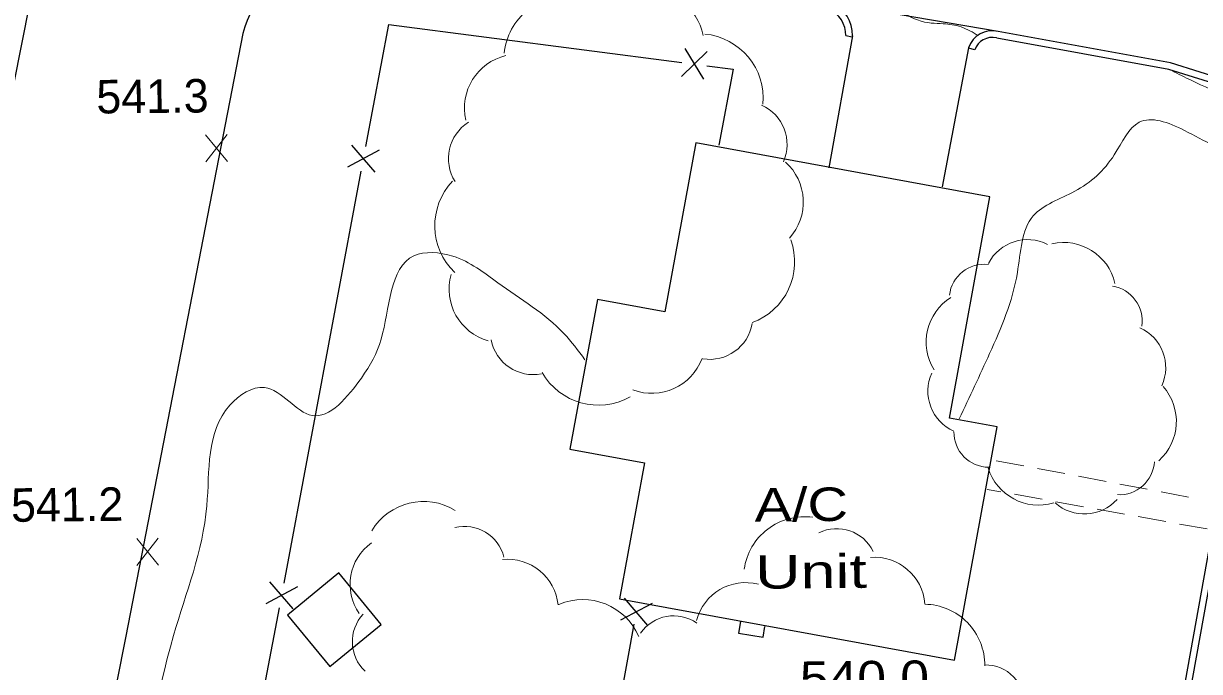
# Model space of a CAD drawing. Extents: x 2361708 to 2370558, y 6977955 to 6991887.
# Drawn here: x 2366425.5 to 2366593.7, y 6983677.6 to 6983770.4 of the extents above; entities that cross this region are included whole.
import ezdxf

# ---------------------------------------------------------------- set-up
doc = ezdxf.new("R2010")
doc.units = 0
doc.header["$LTSCALE"] = 1.9
for name, color, linetype, lineweight in [('11', 7, 'Continuous', 25), ('13', 7, 'Continuous', 13), ('17', 7, 'Continuous', 25), ('2', 7, 'Continuous', 25), ('20', 7, 'Continuous', 25), ('23', 7, 'Continuous', 25), ('29', 7, 'Continuous', 13), ('31', 7, 'Continuous', 13), ('35', 7, 'Continuous', 13)]:
    doc.layers.add(name, color=color, linetype=linetype, lineweight=lineweight)

msp = doc.modelspace()

# ---------------------------------------------------------------- linework, layer by layer
at = {"layer": '11'}
for points in [[(2366557.945, 6983713.908), (2366563.744, 6983745.544), (2366521.668, 6983753.274), (2366517.228, 6983729.091), (2366507.581, 6983730.869), (2366503.644, 6983709.47), (2366514.323, 6983707.512), (2366510.749, 6983688.047), (2366558.664, 6983679.263), (2366564.787, 6983712.653)], [(2366470.601, 6983691.735), (2366463.259, 6983685.685), (2366469.319, 6983678.332), (2366476.662, 6983684.373)]]:
    msp.add_lwpolyline(points, close=True, dxfattribs=at)
at = {"layer": '13'}
for p, q in [((2366568.58, 6983707.059), (2366564.643, 6983707.791)), ((2366574.471, 6983705.945), (2366570.544, 6983706.687)), ((2366580.362, 6983704.831), (2366576.435, 6983705.573)), ((2366563.342, 6983703.699), (2366565.305, 6983703.347)), ((2366567.269, 6983702.996), (2366571.206, 6983702.283)), ((2366586.253, 6983703.717), (2366582.326, 6983704.459)), ((2366592.144, 6983702.603), (2366588.216, 6983703.345)), ((2366573.169, 6983701.932), (2366577.107, 6983701.219)), ((2366579.069, 6983700.868), (2366583.007, 6983700.155)), ((2366584.97, 6983699.804), (2366588.907, 6983699.091)), ((2366590.87, 6983698.74), (2366594.808, 6983698.028))]:
    msp.add_line(p, q, dxfattribs=at)
at = {"layer": '17'}
for p, q in [((2366519.617, 6983762.805), (2366523.303, 6983766.36)), ((2366522.791, 6983762.395), (2366520.13, 6983766.77)), ((2366476.376, 6983752.233), (2366471.849, 6983749.83)), ((2366475.786, 6983749.088), (2366472.438, 6983752.976)), ((2366462.755, 6983690.271), (2366473.804, 6983749.249)), ((2366464.66, 6983689.729), (2366460.133, 6983687.315)), ((2366464.07, 6983686.583), (2366460.723, 6983690.461)), ((2366514.825, 6983684.236), (2366511.468, 6983688.104)), ((2366515.405, 6983687.381), (2366510.888, 6983684.958)), ((2366510.154, 6983669.641), (2366512.853, 6983684.397))]:
    msp.add_line(p, q, dxfattribs=at)
for points in [[(2366474.471, 6983752.785), (2366477.735, 6983770.207), (2366519.659, 6983764.786)], [(2366523.233, 6983764.32), (2366527.008, 6983763.836), (2366524.951, 6983752.935)], [(2366449.807, 6983628.004), (2366460.167, 6983676.465), (2366462.089, 6983686.734)]]:
    msp.add_lwpolyline(points, dxfattribs=at)
at = {"layer": '2'}
for p, q in [((2366564.908, 6983769.227), (2366541.089, 6983773.27)), ((2366544.073, 6983768.608), (2366540.683, 6983749.705)), ((2366543.113, 6983768.639), (2366544.055, 6983768.448)), ((2366560.671, 6983766.886), (2366556.91, 6983746.99)), ((2366561.583, 6983766.585), (2366560.661, 6983766.846)), ((2366586.861, 6983649.24), (2366604.772, 6983749.085)), ((2366587.803, 6983649.069), (2366605.714, 6983748.914))]:
    msp.add_line(p, q, dxfattribs=at)
for points in [[(2366412.45, 6983703.193), (2366434.505, 6983814.108), (2366426.801, 6983813.424), (2366404.245, 6983726.755), (2366372.306, 6983610.926), (2366341.663, 6983499.678), (2366310.838, 6983396.1)], [(2366456.855, 6983768.958), (2366440.106, 6983682.665), (2366424.189, 6983602.459), (2366413.719, 6983550.917), (2366405.327, 6983504.885)], [(2366598.058, 6983762.052), (2366589.572, 6983764.721), (2366564.908, 6983769.227)], [(2366597.767, 6983761.139), (2366589.341, 6983763.789), (2366564.737, 6983768.285)]]:
    msp.add_lwpolyline(points, dxfattribs=at)
for centre, radius, start, end in [((2366477.417, 6983762.96), 21.418, 84.11911, 163.73748), ((2366539.16, 6983768.749), 3.955, 358.35667, 66.89654), ((2366539.16, 6983768.749), 4.915, 358.35667, 66.89654), ((2366564.048, 6983765.778), 3.554, 75.98916, 161.84111), ((2366564.048, 6983765.778), 2.594, 75.98916, 161.84111)]:
    msp.add_arc(centre, radius, start, end, dxfattribs=at)
at = {"layer": '23'}
msp.add_line((2366528.05, 6983684.792), (2366527.786, 6983683.099), dxfattribs=at)
msp.add_lwpolyline([(2366527.786, 6983683.099), (2366531.322, 6983682.553), (2366531.557, 6983684.085)], dxfattribs=at)
at = {"layer": '29'}
for centre, radius, start, end in [((2366503.435, 6983765.141), 9.234, 84.00965, 174.00965), ((2366515.153, 6983767.245), 7.698, 10.67843, 100.67843), ((2366522.076, 6983759.669), 9.234, 354.60882, 84.60882), ((2366496.273, 6983758.29), 7.698, 103.25187, 193.25187), ((2366528.568, 6983753.071), 6.152, 336.02524, 66.02524), ((2366492.432, 6983751.041), 6.152, 122.38701, 212.38701), ((2366529.344, 6983744.814), 7.698, 317.93359, 47.93359), ((2366493.552, 6983741.433), 9.234, 136.33427, 226.33427), ((2366526.57, 6983736.238), 9.234, 289.93585, 19.93585), ((2366569.118, 6983733.155), 6.28, 62.77074, 152.77074), ((2366574.289, 6983731.496), 7.532, 12.895, 102.895), ((2366562.937, 6983730.896), 5.019, 83.29294, 173.29294), ((2366494.073, 6983732.349), 7.698, 164.14525, 254.14525), ((2366580.491, 6983727.819), 5.019, 351.16992, 81.16992), ((2366562.151, 6983724.777), 7.532, 121.97963, 211.97963), ((2366523.656, 6983728.453), 6.152, 260.62154, 350.62154), ((2366582.605, 6983721.114), 6.28, 335.65893, 65.65893), ((2366498.422, 6983726.267), 6.152, 190.91145, 280.91145), ((2366515.369, 6983725.138), 7.698, 249.35327, 339.35327), ((2366507.724, 6983724.977), 9.234, 209.39007, 299.39007), ((2366561.137, 6983717.75), 6.28, 155.82763, 245.82763), ((2366582.885, 6983713.411), 7.532, 311.75515, 41.75515), ((2366563.612, 6983711.881), 5.019, 179.4664, 269.4664), ((2366570.69, 6983708.975), 7.532, 196.88522, 286.88522), ((2366582.268, 6983707.952), 5.019, 266.66531, 356.66531), ((2366482.735, 6983693.263), 8.699, 58.67537, 148.67537), ((2366577.243, 6983706.457), 6.28, 228.16783, 318.16783), ((2366537.209, 6983691.078), 8.699, 82.21467, 172.21467), ((2366488.576, 6983692.603), 5.796, 13.80949, 103.80949), ((2366541.816, 6983692.279), 5.796, 25.92118, 115.92118), ((2366479.448, 6983690.107), 7.253, 125.08288, 215.08288), ((2366494.742, 6983686.443), 7.253, 5.7249, 95.7249), ((2366547.206, 6983686.737), 7.253, 4.45383, 94.45383), ((2366528.779, 6983683.099), 7.253, 75.30159, 165.30159), ((2366505.488, 6983679.231), 8.699, 23.01119, 113.01119), ((2366554.3, 6983678.561), 8.699, 359.28997, 89.28997), ((2366478.323, 6983681.886), 5.796, 136.79738, 226.79738), ((2366518.507, 6983679.805), 5.796, 55.17647, 145.17647), ((2366563.024, 6983672.785), 5.796, 0.00055, 90.00055)]:
    msp.add_arc(centre, radius, start, end, dxfattribs=at)
at = {"layer": '31'}
for p, q in [((2366454.66, 6983750.606), (2366451.543, 6983754.457)), ((2366451.58, 6983750.577), (2366454.623, 6983754.486)), ((2366444.8, 6983692.83), (2366441.683, 6983696.68)), ((2366441.72, 6983692.8), (2366444.763, 6983696.71))]:
    msp.add_line(p, q, dxfattribs=at)
at = {"layer": '35'}
for points in [[(2366634.791, 6983919.569), (2366632.667, 6983912.539), (2366627.202, 6983898.356), (2366624.039, 6983887.106), (2366616.496, 6983871.663), (2366613.136, 6983862.14), (2366609.482, 6983856.205), (2366604.22, 6983852.195), (2366602.436, 6983848.438), (2366604.988, 6983846.192), (2366609.012, 6983842.61), (2366607.842, 6983834.219), (2366604.316, 6983824.374), (2366600.197, 6983816.855), (2366595.104, 6983813.926), (2366586.855, 6983813.848), (2366579.375, 6983814.807), (2366565.709, 6983816.387), (2366552.761, 6983818.243), (2366538.688, 6983819.56), (2366528.389, 6983821.472), (2366516.562, 6983822.139), (2366503.671, 6983825.346), (2366492.754, 6983824.962), (2366486.612, 6983826.254), (2366479.358, 6983831.816), (2366476.585, 6983837.429), (2366473.459, 6983845.36), (2366472.047, 6983851.857), (2366469.955, 6983851.087), (2366464.652, 6983848.116), (2366456.29, 6983849.427), (2366449.947, 6983851.717), (2366444.634, 6983854.106), (2366440.213, 6983856.324), (2366439.877, 6983854.881), (2366437.568, 6983844.288), (2366434.981, 6983834.523), (2366431.199, 6983822.067), (2366424.733, 6983799.634), (2366418.881, 6983780.807), (2366413.681, 6983760.847), (2366407.995, 6983739.342), (2366403.268, 6983718.016), (2366399.542, 6983701.839), (2366394.896, 6983679.284), (2366389.396, 6983656.12), (2366384.274, 6983633.281), (2366382.176, 6983616.25), (2366377.896, 6983593.058), (2366374.864, 6983570.218), (2366370.936, 6983546.83), (2366369.353, 6983533.434), (2366367.804, 6983522.799), (2366367.692, 6983521.998), (2366366.792, 6983516.709), (2366366.128, 6983509.792), (2366367.472, 6983509.385), (2366370.916, 6983514.278), (2366374.314, 6983517.631), (2366381.278, 6983525.637), (2366394.175, 6983533.32), (2366404.166, 6983536.455), (2366409.203, 6983534.753), (2366412.734, 6983529.367), (2366412.225, 6983522.982), (2366409.904, 6983513.569), (2366408.594, 6983499.946), (2366407.465, 6983488.314), (2366406.028, 6983481.58), (2366403.731, 6983476.068)], [(2366485.979, 6983819.178), (2366491.127, 6983816.247), (2366497.776, 6983813.32), (2366506.035, 6983809.238), (2366516.566, 6983804.868), (2366522.554, 6983799.955), (2366522.228, 6983793.232), (2366511.842, 6983788.552), (2366499.129, 6983787.691), (2366484.539, 6983787.642), (2366478.993, 6983786.16), (2366477.97, 6983785.39), (2366469.928, 6983783.543), (2366464.932, 6983781.985), (2366460.007, 6983782.469), (2366451.957, 6983787.693), (2366446.912, 6983795.635), (2366444.296, 6983806.651), (2366442.084, 6983819.48), (2366439.958, 6983825.4), (2366437.556, 6983825.557), (2366435.491, 6983820.757), (2366433.254, 6983812.046), (2366430.05, 6983799.815), (2366424.514, 6983785.841), (2366419.166, 6983764.549), (2366412.066, 6983740.291), (2366405.175, 6983714.073), (2366400.657, 6983691.81), (2366392.571, 6983657.801), (2366386.433, 6983629.101), (2366384.991, 6983612.557), (2366382.778, 6983592.915), (2366378.809, 6983577.036), (2366376.571, 6983564.184), (2366377.538, 6983561.393), (2366376.072, 6983551.529), (2366377.363, 6983549.311), (2366379.325, 6983551.08), (2366383.487, 6983558.33), (2366388.543, 6983565.118), (2366393.945, 6983569.14), (2366402.789, 6983577.104), (2366412.027, 6983583.723), (2366418.005, 6983584.98), (2366420.808, 6983580.446), (2366420.744, 6983570.415), (2366420.747, 6983554.294), (2366418.434, 6983532.531), (2366415.774, 6983515.755), (2366412.918, 6983503.757), (2366410.989, 6983493.138), (2366409.593, 6983483.234), (2366407.334, 6983475.733)], [(2366564.357, 6983805.103), (2366573.894, 6983801.214), (2366584.724, 6983797.137), (2366592.02, 6983794.396), (2366597.447, 6983791.588), (2366601.823, 6983786.759), (2366601.806, 6983782.239), (2366597.508, 6983776.758), (2366590.083, 6983774.137), (2366581.034, 6983772.92), (2366571.363, 6983772.898), (2366560.996, 6983772.64), (2366553.955, 6983772.673), (2366551.048, 6983772.365), (2366553.363, 6983770.877), (2366557.068, 6983770.342), (2366559.622, 6983769.877), (2366562.074, 6983768.64)], [(2366589.813, 6983763.604), (2366592.516, 6983762.239), (2366598.044, 6983759.342), (2366600.986, 6983754.95), (2366599.414, 6983753.044), (2366591.574, 6983755.07), (2366585.093, 6983756.238), (2366581.537, 6983751.594), (2366575.867, 6983746.35), (2366569.93, 6983742.833), (2366567.667, 6983734.711), (2366563.687, 6983723.123), (2366559.365, 6983713.791)], [(2366505.793, 6983722.252), (2366502.797, 6983725.994), (2366493.357, 6983733.254), (2366486.92, 6983737.063), (2366481.32, 6983737.119), (2366476.644, 6983725.185), (2366473.816, 6983719.627), (2366466.757, 6983714.26), (2366459.968, 6983718.276), (2366455.012, 6983715.738), (2366451.709, 6983701.346), (2366446.955, 6983682.8), (2366441.101, 6983655.933), (2366435.701, 6983634.82), (2366430.556, 6983601.74), (2366428.832, 6983575.922), (2366424.705, 6983550.391), (2366425.268, 6983535.306), (2366423.592, 6983521.25), (2366421.032, 6983510.715), (2366418.737, 6983498.562), (2366415.67, 6983486.722), (2366413.814, 6983476.874), (2366412.221, 6983475.059)]]:
    msp.add_spline(points, degree=3, dxfattribs=at)

# ---------------------------------------------------------------- texts
at = {"layer": '20'}
for s, width, p in [('A/C', 1.25, (2366530.084, 6983699.062)), ('Unit', 1.4, (2366530.176, 6983689.462))]:
    msp.add_text(s, height=4.8, rotation=0.545, dxfattribs=dict(at, width=width)).set_placement(p)
at = {"layer": '31'}
for s, p in [('541.3', (2366435.924, 6983757.488)), ('541.2', (2366423.719, 6983699.049))]:
    msp.add_text(s, height=4.8, rotation=0.545, dxfattribs=at).set_placement(p)
at = {"layer": '31', "width": 1.15}
msp.add_text('540.0', height=4.8, rotation=0.545, dxfattribs=at).set_placement((2366536.581, 6983674.253))

doc.saveas('drawing.dxf')
